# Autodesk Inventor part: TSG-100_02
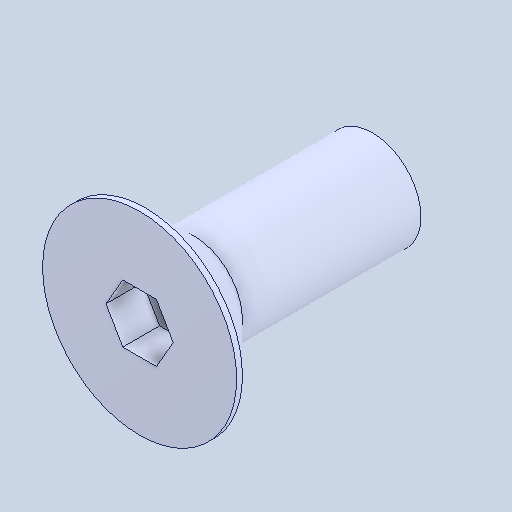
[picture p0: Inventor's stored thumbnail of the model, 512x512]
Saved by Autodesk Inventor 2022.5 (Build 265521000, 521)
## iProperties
Created: 2024-05
Part Number: TSG-100_02
Material: 一般
Document SubType Name: Modeling
Designer: ImaoCorp
Density: 1 g/cm^3
Appearance: 既定
Author: ImaoCorp
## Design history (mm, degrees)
feature "TSG-100_02"
node "ソリッド1"
